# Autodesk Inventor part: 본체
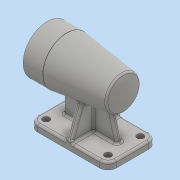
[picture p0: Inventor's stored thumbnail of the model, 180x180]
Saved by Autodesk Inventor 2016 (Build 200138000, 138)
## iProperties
Created: 2018-09
Part Number: 본체
Material: 일반
Document SubType Name: Modeling
Designer: 605-11
Density: 1 g/cm^3
Appearance: 기본값
Author: 605-11
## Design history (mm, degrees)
sketch "스케치1"
  geometry: 1 further point
sketch "스케치2"
  geometry: L1 (56, -35)-(-56, -35); L2 (-56, -35)-(-56, 35); L3 (-56, 35)-(56, 35); L4 (56, 35)-(56, -35); L5 (56, -35)-(-56, 35); L6 (-56, -35)-(56, 35); 1 further point
  constraints: 12 end point, 2 midpoint, 2 parallel, 1 horizontal, 1 perpendicular
  dimensions: "d0" = 112 distance of L1.start L1.end; "d1" = 70 distance of L1.end L2.end
extrude "돌출1" new body sketch "스케치2" distance "d2" = 10; taper "d3" = 0 deg
fillet "모깎기1" dims "d4" = 12
sketch "스케치3"
  geometry: L1 (56, -23)-(56, 23) reference; L2 (44, 35)-(-44, 35) reference; L3 (-56, 23)-(-56, -23) reference; L4 (-44, -35)-(44, -35) reference; A1 r 12 centre (44, -23) between (44, -35) and (56, -23) reference; A2 r 12 centre (-44, 23) between (-44, 35) and (-56, 23) reference; A3 r 12 centre (-44, -23) between (-56, -23) and (-44, -35) reference; A4 r 12 centre (44, 23) between (56, 23) and (44, 35) reference; 5 further points
  constraints: 4 coincident
hole "구멍1" sketch "스케치3" at (44, -23), (44, 23), (-44, 23), (-44, -23) diameter "d5" = 5.5; stored, may be unused: countersink angle "d9" = 90 deg, drill point angle "d11" = 118 deg; dims "d6" = 6, "d7" = 9.5, "d8" = 5.4, "d10" = 8
sketch "스케치5"
  geometry: L1 (-18.771, 81.764)-(-38, 10); L2 (38, 81.764)-(38, 10); L3 (56, 10)-(56, 0) reference; L4 (-56, 0)-(-56, 10) reference; L5 (44, 10)-(-44, 10) reference; L6 (-38, 10)-(38, 10); L7 (39.25, 10)-(48.75, 10) reference; L8 (38, 81.764)-(-18.771, 81.764); 1 further point
  constraints: 8 end point, 2 point on line, 1 collinear, 1 horizontal, 1 vertical
  dimensions: "d12" = 18 distance between parallel lines of L3 L2; "d13" = 18 distance from line of L1.end L4; "d16" = 105 deg angle of L1 L5; "d17" = 56.77093 distance of L2.start L1.start
extrude "돌출2" join sketch "스케치5" stored distance "d18" = 8; taper "d19" = 0 deg
sketch "스케치6"
  geometry: L1 (0, -35)-(10, -35) reference; L2 (10, 35)-(0, 35) reference; L3 (10, -35)-(77.066, -10.59); L4 (77.066, -10.59)-(77.066, 10.59); L5 (77.066, 10.59)-(10, 35); L6 (10, -35)-(10, 35); 1 further point
  constraints: 8 end point, 2 vertical
  dimensions: "d21" = 20 deg angle of L3 L1; "d22" = 20 deg angle of L5 L2
extrude "돌출3" join sketch "스케치6" stored distance "d23" = 8; taper "d24" = 0 deg
sketch "스케치7"
  geometry: L1 (-49.61, 74)-(77.985, 74); L2 (65.731, 108)-(37.731, 108); L3 (37.731, 108)-(-42.539, 98.144); L4 (-46.269, 74)-(65.731, 74); L5 (65.731, 108)-(65.731, 74); A1 r 80 centre (33.731, 74) between (-42.539, 98.144) and (-46.269, 74); 1 further point
  constraints: 10 end point, 3 point on line, 2 horizontal, 2 point on circle, 1 centre point, 1 collinear, 1 perpendicular
  dimensions: "d25" = 74 distance from line of L1 point (0, 0); "d26" = 68 diameter of L2 L1; "d27" = 28 distance of L2.start L2.end; "d31" = 80 radius of A1; "d32" = 112 horizontal distance of L2.start L4.start; "d33" = 7 deg angle of L3 L2
revolve "회전1" sketch "스케치7" stored, may be unused: angle "d55" = 90 deg
sketch "스케치8"
  geometry: L1 (-71.135, 74)-(104.549, 74); L2 (65.731, 40)-(65.731, 108) reference; L3 (65.731, 74)-(50.731, 74); L4 (50.731, 74)-(50.731, 95); L5 (50.731, 95)-(65.731, 95); L6 (65.731, 95)-(65.731, 74); L7 (50.731, 74)-(-3.269, 74); L8 (-3.269, 74)-(-3.269, 98); L9 (-3.269, 98)-(50.731, 98); L10 (50.731, 98)-(50.731, 74); L11 (-3.269, 74)-(-15.269, 74); L12 (-15.269, 74)-(-15.269, 95); L13 (-15.269, 95)-(-3.269, 95); L14 (-3.269, 95)-(-3.269, 74); L15 (-15.269, 74)-(-33.269, 74); L16 (-33.269, 74)-(-33.269, 91.5); L17 (-33.269, 91.5)-(-15.269, 91.5); L18 (-15.269, 91.5)-(-15.269, 74); L19 (-33.269, 74)-(-37.269, 74); L20 (-37.269, 74)-(-37.269, 90); L21 (-37.269, 90)-(-33.269, 90); L22 (-33.269, 90)-(-33.269, 74); L23 (-37.269, 74)-(-40.269, 74); L24 (-40.269, 74)-(-40.269, 84.5); L25 (-40.269, 84.5)-(-37.269, 84.5); L26 (-37.269, 84.5)-(-37.269, 74); 1 further point
  constraints: 50 end point, 12 parallel, 7 horizontal, 6 perpendicular, 1 midpoint, 1 point on line
  dimensions: "d56" = 74 distance from line of L1 point (0, 0); "d57" = 15 distance of L4.end L5.end; "d58" = 54 distance of L8.end L9.end; "d59" = 12 distance of L12.end L13.end; "d60" = 18 distance of L16.end L17.end; "d61" = 4 distance of L20.end L21.end; "d62" = 3 distance of L24.end L25.end; "d63" = 42 diameter of L5 L1; "d64" = 48 diameter of L9 L1; "d65" = 35 diameter of L17 L1; "d66" = 32 diameter of L21 L1; "d67" = 21 diameter of L25 L1
revolve "회전2" sketch "스케치8" stored, may be unused: angle "d68" = 90 deg
sketch "스케치9"
  geometry: C1 r 34 at (0, 0) reference; 2 further points
  constraints: 1 vertical alignment
  dimensions: "d69" = 26 distance of point (0, 26) C1.centre
hole "구멍2" sketch "스케치9" at (0, 26) diameter "d70" = 3.242; stored, may be unused: countersink angle "d74" = 90 deg, drill point angle "d76" = 118 deg; dims "d71" = 8, "d72" = 19.05, "d73" = 4.775, "d75" = 11
sketch "스케치10"
  geometry: L1 (100, 0)-(100, 10) reference; 2 further points
  constraints: 1 other
  dimensions: "d80" = 56 distance from line of point (44, 3) L1; "d81" = 3 vertical distance of L1.start point (44, 3)
fillet "모깎기2" dims "d82" = 3
fillet "모깎기3" dims "d83" = 0.3, "d84" = 3
fillet "모깎기4" dims "d85" = 3
fillet "모깎기5" dims "d86" = 3
fillet "모깎기6" dims "d87" = 3
chamfer "모따기1" distance "d88" = 1; stored, may be unused: second distance "d89" = 2, angle "d90" = 45 deg
feature "엠보싱1" dims "d0" = 112, "d1" = 70, "d92" = 0.5, "d93" = 0
fillet "모깎기8" dims "d94" = 3
fillet "모깎기9" dims "d95" = 3
fillet "모깎기10" dims "d96" = 3
node "솔리드1"
pattern_circular "원형 패턴1" dims angle "d78" = 360 deg
node "투영된 루프1"
